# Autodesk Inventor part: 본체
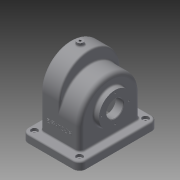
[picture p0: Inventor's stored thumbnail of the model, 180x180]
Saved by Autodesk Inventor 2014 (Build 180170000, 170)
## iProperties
Created: 2017-11
Part Number: 본체
Material: 일반
Document SubType Name: Modeling
Designer: net
Density: 1 g/cm^3
Appearance: 기본값
Author: net
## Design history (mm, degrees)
sketch "스케치1"
  geometry: L1 (0, 0)-(110, 0); L2 (110, 0)-(110, 15); L3 (110, 15)-(0, 15); L4 (0, 15)-(0, 0)
  constraints: 8 end point, 2 parallel, 1 horizontal, 1 perpendicular
  dimensions: "d0" = 110 distance of L1.start L1.end; "d1" = 15 distance of L3.end L1.start
extrude "돌출1" new body sketch "스케치1" stored distance "d2" = 150; taper "d3" = 0 deg
node "작업 평면1"
sketch "스케치2"
  geometry: L1 (0, 0)-(150, 0) reference; L2 (0, 0)-(150, 0) reference; L3 (0, 15)-(0, 0) reference; L4 (150, 15)-(0, 15) reference; L5 (150, 0)-(150, 15) reference; L6 (17, 15)-(17, 57); L7 (133, 57)-(133, 15); L8 (150, 0)-(0, 0) reference; A1 r 58 centre (75, 57) between (85.724, 0) and (64.276, 0); 3 further points
  constraints: 4 end point, 4 point on circle, 4 point on line, 2 midpoint, 2 tangent, 1 centre point, 1 parallel, 1 perpendicular, 1 vertical alignment
  dimensions: "d6" = 116 diameter of A1; "d7" = 57 distance of point (75, 0) A1.centre
extrude "돌출2" join sketch "스케치2" stored distance "d8" = 76; taper "d9" = 0 deg
sketch "스케치3"
  geometry: L1 (0, 0)-(150, 0) reference; L2 (0, 15)-(0, 0) reference; L3 (150, 15)-(0, 15) reference; L4 (150, 0)-(150, 15) reference; L5 (17, 15)-(133, 15) reference; L6 (17, 15)-(17, 57) reference; L7 (133, 57)-(133, 15) reference; L8 (17, 15)-(17, 80); L9 (133, 15)-(133, 80); L10 (17, 15)-(133, 15); A1 r 58 centre (75, 80) between (17, 80) and (133, 80); A2 r 58 centre (75, 57) between (133, 57) and (17, 57) reference; 2 further points
  constraints: 6 end point, 2 point on circle, 1 centre point, 1 collinear, 1 midpoint, 1 parallel, 1 tangent, 1 vertical alignment
  dimensions: "d10" = 116 diameter of A1; "d11" = 80 distance from line of L1 A1.centre
extrude "돌출3" join sketch "스케치3" distance "d12" = 38; taper "d13" = 0 deg
node "작업 평면2"
sketch "스케치4"
  geometry: L1 (-17, -17)-(-17, -133) reference; L2 (-17, -133)-(-93, -133) reference; L3 (-93, -133)-(-93, -17) reference; L4 (-93, -17)-(-17, -17) reference; L5 (-110, 0)-(0, 0) reference; L6 (-110, -150)-(-110, 0) reference; L7 (0, -150)-(-110, -150) reference; L8 (0, -150)-(0, 0) reference; L9 (-55, -133)-(-55, -17) reference; L10 (-93, -17)-(-55, -17) reference; L11 (-93, -133)-(-93, -17) reference; L12 (-55, -133)-(-93, -133) reference; L13 (-55, -17)-(-17, -17) reference; C1 r 6 at (-36, -75); 3 further points
  constraints: 2 midpoint, 1 centre point, 1 horizontal alignment, 1 vertical alignment
  dimensions: "d15" = 12 diameter of C1
extrude "돌출4" join sketch "스케치4" stored distance "d16" = 38; taper "d17" = 0 deg
sketch "스케치5"
  geometry: L1 (150, 15)-(0, 15) reference; L2 (0, 0)-(0, 15) reference; L3 (150, 0)-(0, 0) reference; L4 (150, 15)-(150, 0) reference; L5 (150, 0)-(0, 0) reference; C1 r 31 at (75, 65); 2 further points
  constraints: 1 centre point, 1 midpoint, 1 vertical alignment
  dimensions: "d18" = 65 distance from line of C1.centre L3; "d19" = 62 diameter of C1
extrude "돌출5" join sketch "스케치5" distance "d20" = 10; taper "d21" = 0 deg
sketch "스케치6"
  geometry: L1 (0, 0)-(-150, 0) reference; L2 (0, 15)-(0, 0) reference; L3 (-150, 15)-(0, 15) reference; L4 (-150, 0)-(-150, 15) reference; L5 (0, 0)-(-150, 0) reference; C1 r 37.5 at (-75, 65); 3 further points
  constraints: 2 midpoint, 1 centre point, 1 vertical alignment
  dimensions: "d22" = 75 diameter of C1; "d23" = 65 distance from line of C1.centre L1
extrude "돌출6" join sketch "스케치6" distance "d24" = 9; taper "d25" = 0 deg
node "작업 평면3"
sketch "스케치8"
  geometry: L1 (17, 15)-(133, 15) reference; L2 (17, 15)-(17, 80) reference; L3 (133, 80)-(133, 15) reference; L4 (22, 80)-(22, 20); L5 (128, 20)-(128, 80); L6 (22, 20)-(22, -3.891); L7 (128, -3.891)-(128, 20); L8 (22, -3.891)-(128, -3.891); C1 r 37.5 at (75, 65) reference; A1 r 58 centre (75, 80) between (133, 80) and (17, 80) reference; A2 r 53 centre (75, 80) between (128, 80) and (22, 80); 2 further points
  constraints: 10 end point, 2 perpendicular, 2 point on circle, 1 centre point, 1 parallel, 1 vertical alignment, 1 other
  dimensions: "d37" = 5 distance between parallel lines of L4 L2; "d38" = 5 distance between parallel lines of L5 L3; "d39" = 18.8909 distance between parallel lines of L1 L8
extrude "돌출7" cut sketch "스케치8" distance "d40" = 28; taper "d41" = 0 deg
node "작업 평면4"
sketch "스케치9"
  geometry: L1 (0, 0)-(150, 0) reference; L2 (0, 15)-(0, 0) reference; L3 (150, 15)-(0, 15) reference; L4 (150, 0)-(150, 15) reference; L5 (133, 80)-(133, 15) reference; L6 (17, 15)-(17, 80) reference; L7 (22, -7.753)-(22, 57); L8 (128, 57)-(128, -7.753); L9 (22, -7.753)-(128, -7.753); A1 r 58 centre (75, 57) between (133, 57) and (17, 57) reference; A2 r 53 centre (75, 57) between (128, 57) and (22, 57); 1 further point
  constraints: 6 end point, 3 parallel, 2 point on circle, 1 centre point, 1 perpendicular
  dimensions: "d43" = 5 distance between parallel lines of L7 L6; "d44" = 5 distance between parallel lines of L5 L8; "d45" = 5 radial gap between concentric circles of A1 A2; "d46" = 7.75265 distance between parallel lines of L1 L9
extrude "돌출8" cut sketch "스케치9" distance "d47" = 28; taper "d49" = 0 deg; dims "d48" = 14, "d50" = 0
hole "구멍1" diameter "d53" = 32; stored, may be unused: countersink angle "d57" = 90 deg, drill point angle "d59" = 118 deg; dims "d51" = 10, "d52" = 10, "d54" = 6, "d55" = 4, "d56" = 2, "d58" = 8
sketch "스케치10"
  geometry: C1 r 16 at (0, 0) reference; 2 further points
  constraints: 1 vertical alignment
  dimensions: "d60" = 26 distance of point (0, 26) C1.centre
hole "구멍2" sketch "스케치10" at (0, 26) diameter "d61" = 2.459; stored, may be unused: countersink angle "d65" = 90 deg, drill point angle "d67" = 118 deg; dims "d62" = 6, "d63" = 4, "d64" = 2, "d66" = 8
sketch "스케치11"
  geometry: C1 r 16 at (0, 0) reference; 2 further points
  constraints: 1 vertical alignment
  dimensions: "d71" = 29 distance of point (0, 29) C1.centre
hole "구멍3" sketch "스케치11" at (0, 29) diameter "d72" = 2.459; stored, may be unused: countersink angle "d76" = 90 deg, drill point angle "d78" = 118 deg; dims "d73" = 6, "d74" = 4, "d75" = 2, "d77" = 8
hole "구멍4" diameter "d84" = 4.134; stored, may be unused: countersink angle "d88" = 90 deg, drill point angle "d90" = 118 deg; dims "d85" = 6, "d86" = 4, "d87" = 2, "d89" = 8, "d120" = 10, "d121" = 10
sketch "스케치12"
  geometry: L1 (110, 0)-(0, 0) reference; L2 (0, 150)-(0, 0) reference; 2 further points
  dimensions: "d92" = 12 distance from line of point (12, 12) L1; "d93" = 12 distance from line of L2 point (12, 12)
fillet "모깎기1" dims "d91" = 12
hole "구멍5" sketch "스케치12" diameter "d94" = 5; stored, may be unused: countersink angle "d98" = 90 deg, drill point angle "d100" = 118 deg; dims "d95" = 6, "d96" = 12, "d97" = 5, "d99" = 8
chamfer "모따기1" distance "d107" = 1; stored, may be unused: second distance "d108" = 2, angle "d109" = 45 deg
fillet "모깎기2" dims "d110" = 3
fillet "모깎기3" dims "d111" = 3
fillet "모깎기4" dims "d112" = 3
fillet "모깎기6" dims "d114" = 8
fillet "모깎기7" dims "d115" = 3
sketch "스케치13"
  geometry: L1 (-35, 23)-(-35, -39) reference; L2 (-40, -57)-(46, -57) reference; 2 further points
  constraints: 1 other
  dimensions: "d116" = 38 distance from line of point (3, -17) L1; "d117" = 40 distance from line of point (3, -17) L2
feature "엠보싱1" sketch "스케치13" dims "d118" = 0.5, "d119" = 0
fillet "모깎기5" dims "d113" = 3
sketch "스케치7"
  geometry: L1 (17, 138)-(17, 80) reference; L2 (17, 27.5)-(17, 102.5) reference; L3 (17, 80)-(17, 15) reference; L4 (93, 15)-(93, 57) reference; L5 (93, 96)-(93, 34) reference; L6 (93, 57)-(93, 115) reference; L7 (55, 115)-(93, 115) reference; L8 (55, 80)-(55, 138) reference; L9 (55, 138)-(17, 138) reference; L10 (50, 133)-(22, 133); L11 (22, 133)-(22, 0); L12 (50, 0)-(50, 133); L13 (50, 110)-(88, 110); L14 (88, 0)-(88, 110); L15 (88, 57)-(50, 57); L16 (50, 80)-(22, 80); L17 (110, 0)-(0, 0) reference; L18 (22, 0)-(88, 0)
  constraints: 16 end point, 5 parallel, 5 point on line, 3 perpendicular, 2 collinear
  dimensions: "d26" = 5 distance between parallel lines of L7 L13; "d27" = 5 distance between parallel lines of L14 L6; "d28" = 5 distance between parallel lines of L10 L9; "d29" = 5 distance between parallel lines of L11 L1; "d30" = 5 distance between parallel lines of L8 L12; "d31" = 57 distance between parallel lines of L17 L15; "d32" = 80 distance between parallel lines of L16 L17
revolve "회전1" stored, may be unused: angle "d33" = 90 deg
revolve "회전2" stored, may be unused: angle "d34" = 90 deg
node "솔리드1"
pattern_circular "원형 패턴1" dims angle "d69" = 360 deg
pattern_circular "원형 패턴2" dims angle "d80" = 360 deg
pattern_linear "직사각형 패턴1" dims "d103" = 86, "d106" = 126
node "투영된 루프1"
node "투영된 루프2"
node "투영된 루프3"
node "투영된 루프4"
node "투영된 루프5"
node "투영된 루프6"
node "투영된 루프7"
node "투영된 루프8"
node "투영된 루프9"
other parameters: "d14" = -144, "d35" = -5, "d42" = 5
